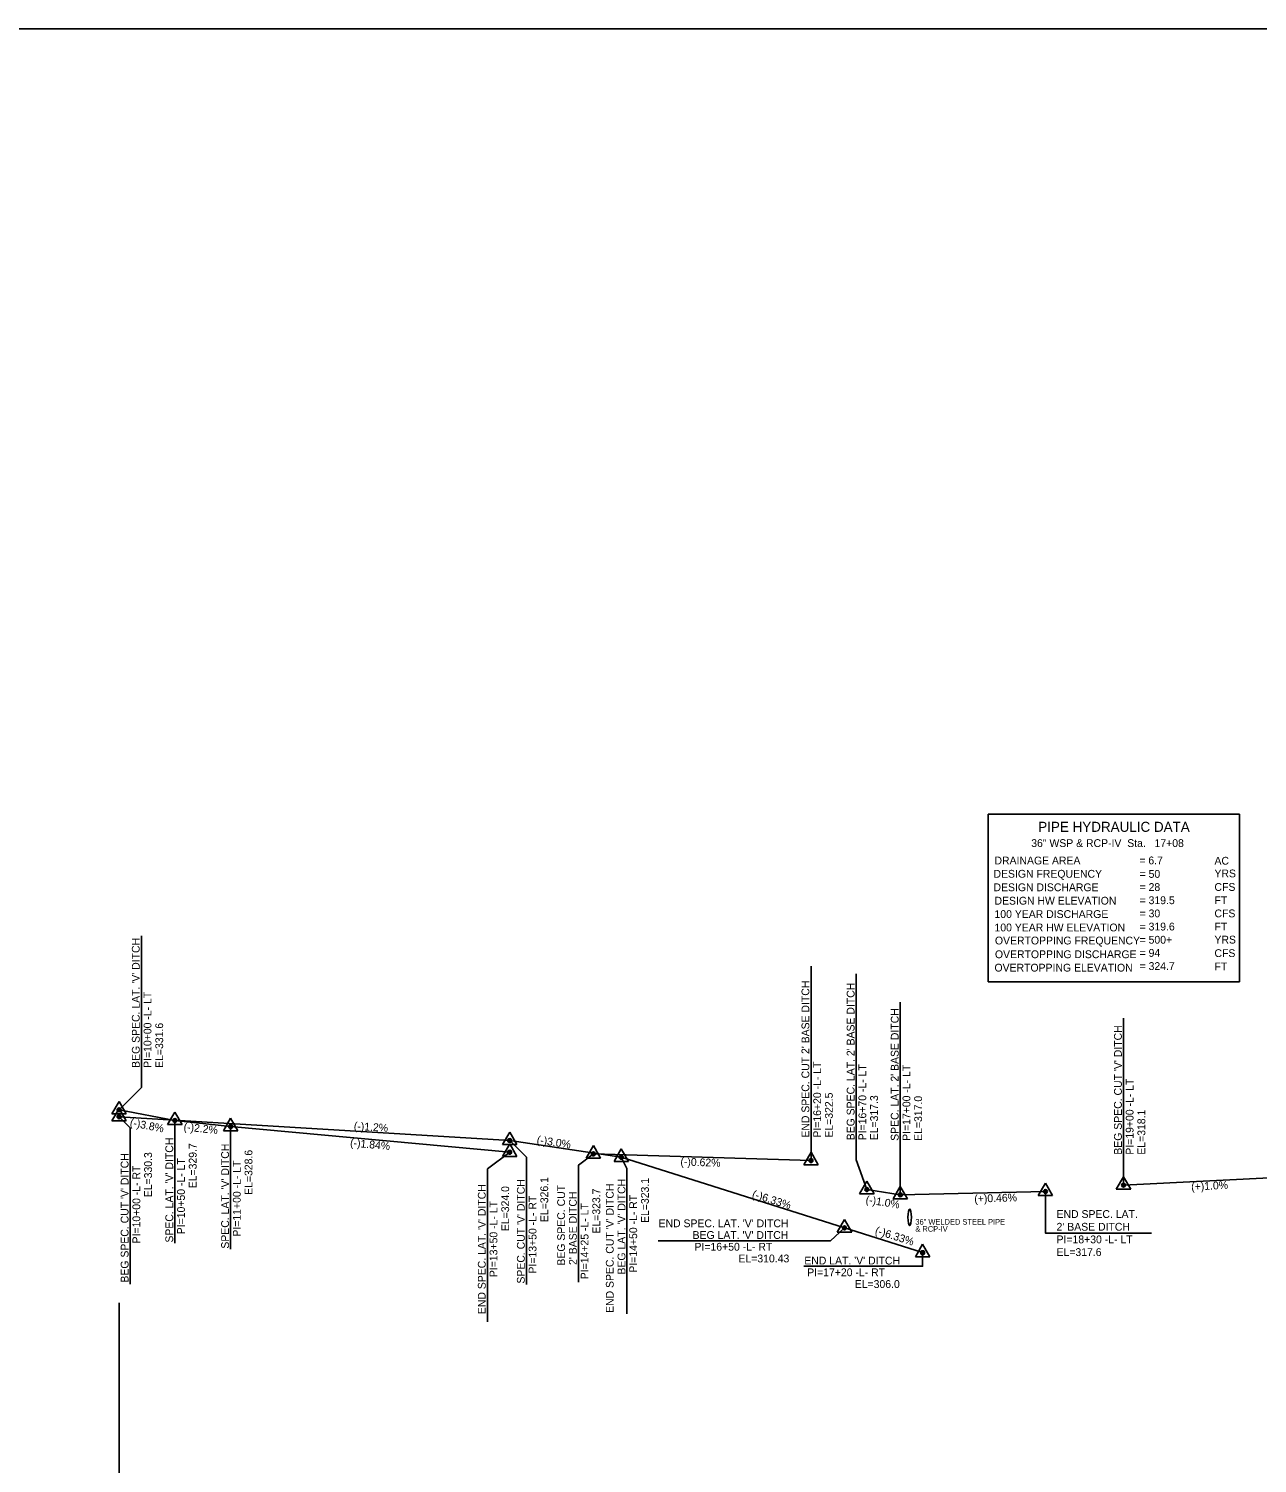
# Model space of a CAD drawing. Extents: x 2110519 to 2119088, y 667494 to 672447.
# Drawn here: x 2112646 to 2113747, y 671161 to 672447 of the extents above; entities that cross this region are included whole.
import ezdxf

# ---------------------------------------------------------------- set-up
doc = ezdxf.new("R2010")
doc.units = 0
for name, color, linetype in [('Exist Horizontal Alignment', 7, 'Continuous'), ('Old_Level_1', 7, 'Continuous'), ('Old_Level_2', 7, 'Continuous'), ('Prop Conc 1ft 6in Curb and Gutter', 7, 'Continuous'), ('Prop Conc 5in Monolithic Surface Mount Island', 7, 'Continuous'), ('Prop Conc Curb 8in x 18in', 7, 'Continuous'), ('Prop EOT', 7, 'Continuous'), ('Prop Paved Shoulder', 7, 'Continuous'), ('Scratch_Level_4', 7, 'Continuous')]:
    doc.layers.add(name, color=color, linetype=linetype)

msp = doc.modelspace()

# ---------------------------------------------------------------- linework, layer by layer
at = {"layer": 'Exist Horizontal Alignment'}
msp.add_line((2112826.7, 671463.2), (2113076.7, 671440.2), dxfattribs=at)
msp.add_lwpolyline([(2110519.2, 672447), (2115845.7, 672447), (2115845.7, 670168.2), (2110519.2, 670168.2)], close=True, dxfattribs=at)
at = {"layer": 'Old_Level_1'}
for p, q in [((2113346.7, 671432.7), (2113346.7, 671606.8)), ((2113626.7, 671410.7), (2113626.7, 671560.4)), ((2112726.7, 671485.7), (2112720.2, 671474.5)), ((2112726.7, 671485.7), (2112733.2, 671474.5)), ((2112720.2, 671474.5), (2112733.2, 671474.5)), ((2112776.7, 671476.1), (2112770.2, 671464.9)), ((2112776.7, 671476.1), (2112783.2, 671464.9)), ((2112776.7, 671468.6), (2112776.7, 671358.6)), ((2112826.7, 671470.7), (2112820.2, 671459.5)), ((2112826.7, 671470.7), (2112833.2, 671459.5)), ((2112770.2, 671464.9), (2112783.2, 671464.9)), ((2112820.2, 671459.5), (2112833.2, 671459.5)), ((2112826.7, 671463.2), (2112826.7, 671353.2)), ((2113076.7, 671447.7), (2113070.2, 671436.5)), ((2113076.7, 671447.7), (2113083.2, 671436.5)), ((2113151.7, 671446.2), (2113145.2, 671435)), ((2113151.7, 671446.2), (2113158.2, 671435)), ((2113070.2, 671436.5), (2113083.2, 671436.5)), ((2113145.2, 671435), (2113158.2, 671435)), ((2113346.7, 671440.2), (2113340.2, 671429)), ((2113340.2, 671429), (2113353.2, 671429)), ((2113346.7, 671440.2), (2113353.2, 671429)), ((2113626.7, 671418.2), (2113620.2, 671407)), ((2113626.7, 671418.2), (2113633.2, 671407)), ((2113396.7, 671414.2), (2113390.2, 671403)), ((2113390.2, 671403), (2113403.2, 671403)), ((2113396.7, 671414.2), (2113403.2, 671403)), ((2113426.7, 671409.5), (2113420.2, 671398.3)), ((2113426.7, 671409.5), (2113433.2, 671398.3)), ((2113556.7, 671412.5), (2113550.2, 671401.3)), ((2113556.7, 671412.5), (2113563.2, 671401.3)), ((2113620.2, 671407), (2113633.2, 671407)), ((2113420.2, 671398.3), (2113433.2, 671398.3)), ((2113550.2, 671401.3), (2113563.2, 671401.3)), ((2112726.7, 670820.2), (2112726.7, 671305.2))]:
    msp.add_line(p, q, dxfattribs=at)
for points in [[(2112726.7, 671478.2), (2112746.7, 671498.2), (2112746.7, 671634.2)], [(2113396.7, 671406.7), (2113387.2, 671433.3), (2113387.2, 671600.1)], [(2113426.7, 671402), (2113426.7, 671574.6)], [(2113076.7, 671440.2), (2113056.7, 671425.2), (2113056.7, 671288.2)], [(2113151.7, 671438.7), (2113138.4, 671428.7), (2113138.4, 671323.8)], [(2113556.7, 671405), (2113556.7, 671367.7), (2113651.8, 671367.7)]]:
    msp.add_lwpolyline(points, dxfattribs=at)
for centre, radius in [((2112726.7, 671478.2), 1.75), ((2112726.7, 671478.2), 1.2), ((2112726.7, 671478.2), 0.5), ((2112776.7, 671468.6), 1.75), ((2112776.7, 671468.6), 1.2), ((2112776.7, 671468.6), 0.5), ((2112826.7, 671463.2), 1.75), ((2112826.7, 671463.2), 1.2), ((2112826.7, 671463.2), 0.5), ((2113076.7, 671440.2), 1.75), ((2113076.7, 671440.2), 1.2), ((2113076.7, 671440.2), 0.5), ((2113151.7, 671438.7), 1.75), ((2113151.7, 671438.7), 1.2), ((2113151.7, 671438.7), 0.5), ((2113346.7, 671432.7), 1.75), ((2113346.7, 671432.7), 1.2), ((2113346.7, 671432.7), 0.5), ((2113396.7, 671406.7), 1.75), ((2113396.7, 671406.7), 1.2), ((2113396.7, 671406.7), 0.5), ((2113426.7, 671402), 1.75), ((2113426.7, 671402), 1.2), ((2113426.7, 671402), 0.5), ((2113556.7, 671405), 1.75), ((2113556.7, 671405), 1.2), ((2113556.7, 671405), 0.5), ((2113626.7, 671410.7), 1.75), ((2113626.7, 671410.7), 1.2), ((2113626.7, 671410.7), 0.5)]:
    msp.add_circle(centre, radius, dxfattribs=at)
at = {"layer": 'Old_Level_2'}
for p, q in [((2113151.7, 671438.7), (2113346.7, 671432.7)), ((2113626.7, 671410.7), (2113776.7, 671418.2)), ((2113396.7, 671406.7), (2113426.7, 671402)), ((2113426.7, 671402), (2113556.7, 671405))]:
    msp.add_line(p, q, dxfattribs=at)
msp.add_lwpolyline([(2112726.7, 671478.2), (2112776.7, 671468.6), (2112826.7, 671463.2), (2113076.7, 671440.2)], dxfattribs=at)
at = {"layer": 'Prop Conc Curb 8in x 18in'}
msp.add_lwpolyline([(2113505.5, 671593), (2113730.5, 671593), (2113730.5, 671743), (2113505.5, 671743)], close=True, dxfattribs=at)
at = {"layer": 'Prop EOT'}
msp.add_lwpolyline([(2112726.7, 671472), (2113076.7, 671450.7), (2113176.7, 671435.7), (2113446.7, 671350.2)], dxfattribs=at)
at = {"layer": 'Prop Paved Shoulder'}
msp.add_ellipse((2113435.1, 671381.9), major_axis=(0, 7.5), ratio=0.2, dxfattribs=at)
at = {"layer": 'Scratch_Level_4'}
for p, q in [((2112726.7, 671479.5), (2112720.2, 671468.3)), ((2112720.2, 671468.3), (2112733.2, 671468.3)), ((2112726.7, 671479.5), (2112733.2, 671468.3)), ((2113076.7, 671458.2), (2113070.2, 671447)), ((2113076.7, 671458.2), (2113083.2, 671447)), ((2113070.2, 671447), (2113083.2, 671447)), ((2113176.7, 671443.2), (2113170.2, 671432)), ((2113176.7, 671443.2), (2113183.2, 671432)), ((2113170.2, 671432), (2113183.2, 671432)), ((2113376.7, 671379.9), (2113370.2, 671368.7)), ((2113376.7, 671379.9), (2113383.2, 671368.7)), ((2113376.7, 671372.4), (2113364.1, 671360.8)), ((2113370.2, 671368.7), (2113383.2, 671368.7)), ((2113364.1, 671360.8), (2113209.8, 671360.8)), ((2113446.7, 671357.7), (2113440.2, 671346.5)), ((2113446.7, 671357.7), (2113453.2, 671346.5)), ((2113440.2, 671346.5), (2113453.2, 671346.5))]:
    msp.add_line(p, q, dxfattribs=at)
for points in [[(2112726.7, 671472), (2112736.7, 671462), (2112736.7, 671322)], [(2113076.7, 671450.7), (2113091.7, 671435.7), (2113091.7, 671321.7)], [(2113176.7, 671435.7), (2113181.7, 671425.7), (2113181.7, 671295.5)], [(2113446.7, 671350.2), (2113446.7, 671338.1), (2113340.3, 671338.1)]]:
    msp.add_lwpolyline(points, dxfattribs=at)
for centre, radius in [((2112726.7, 671472), 1.75), ((2112726.7, 671472), 1.2), ((2112726.7, 671472), 0.5), ((2113076.7, 671450.7), 1.75), ((2113076.7, 671450.7), 1.2), ((2113076.7, 671450.7), 0.5), ((2113176.7, 671435.7), 1.75), ((2113176.7, 671435.7), 1.2), ((2113176.7, 671435.7), 0.5), ((2113376.7, 671372.4), 1.75), ((2113376.7, 671372.4), 1.2), ((2113376.7, 671372.4), 0.5), ((2113446.7, 671350.2), 1.75), ((2113446.7, 671350.2), 1.2), ((2113446.7, 671350.2), 0.5)]:
    msp.add_circle(centre, radius, dxfattribs=at)

# ---------------------------------------------------------------- texts
at = {"layer": 'Old_Level_1'}
for s, rotation, p in [("BEG SPEC. LAT. 'V' DITCH ", 90, (2112745.2, 671515.8)), ('PI=10+00 -L- LT', 90, (2112755.7, 671515.8)), ("END SPEC. CUT 2' BASE DITCH ", 90, (2113345.2, 671453.3)), ("BEG SPEC. LAT. 2' BASE DITCH ", 90, (2113385.7, 671450.9)), ("SPEC. LAT. 2' BASE DITCH ", 90, (2113425.2, 671450.4)), ('EL=331.6', 90, (2112766.2, 671515.8)), ("BEG SPEC. CUT 'V' DITCH ", 90, (2113625.2, 671438)), ('PI=16+20 -L- LT', 90, (2113355.7, 671453.3)), ('PI=16+70 -L- LT', 90, (2113396.2, 671450.9)), ('PI=17+00 -L- LT', 90, (2113435.7, 671450.4)), ('PI=19+00 -L- LT', 90, (2113635.7, 671438)), ('EL=322.5', 90, (2113366.2, 671453.3)), ('EL=317.3', 90, (2113406.7, 671450.9)), ('EL=317.0', 90, (2113446.2, 671450.4)), ('(-)3.8%', 349.0671, (2112736, 671463.7)), ('(-)2.2%', 353.902, (2112784.3, 671459.7)), ('EL=318.1', 90, (2113646.2, 671438)), ("SPEC. LAT. 'V' DITCH ", 90, (2112775.2, 671359.2)), ('EL=329.7', 90, (2112796.2, 671407.9)), ("SPEC. LAT. 'V' DITCH ", 90, (2112825.2, 671353.8)), ('EL=328.6', 90, (2112846.2, 671402)), ('(-)1.84%', 354.7436, (2112933.5, 671445.4)), ('PI=10+50 -L- LT', 90, (2112785.7, 671366.7)), ('PI=11+00 -L- LT', 90, (2112835.7, 671364.6)), ("END SPEC. LAT. 'V' DITCH ", 90, (2113055.2, 671295.1)), ('EL=324.0', 90, (2113076.2, 671369.5)), ('BEG SPEC. CUT ', 90, (2113126.3, 671338.6)), ("2' BASE DITCH ", 90, (2113136.8, 671339.2)), ('EL=323.7', 90, (2113157.8, 671367.3)), ('PI=13+50 -L- LT', 90, (2113065.7, 671328.3)), ('PI=14+25 -L- LT', 90, (2113147.3, 671326.4))]:
    msp.add_text(s, height=7, rotation=rotation, dxfattribs=at).set_placement(p)
for s, p in [("2' BASE DITCH", (2113566.7, 671369.9)), ('END SPEC. LAT.', (2113566.7, 671381.3)), ('PI=18+30 -L- LT', (2113566.7, 671358.6)), ('EL=317.6', (2113566.7, 671347.2))]:
    msp.add_text(s, height=7, dxfattribs=at).set_placement(p)
at = {"layer": 'Old_Level_2'}
for s, rotation, p in [('(-)0.62%', 358.2376, (2113229.6, 671428.3)), ('(+)0.46%', 1.8413, (2113493.1, 671395)), ('(+)1.0%', 2.8624, (2113687.5, 671405.8)), ('(-)1.0%', 351.096, (2113395.3, 671394.5))]:
    msp.add_text(s, height=7, rotation=rotation, dxfattribs=at).set_placement(p)
at = {"layer": 'Prop Conc 1ft 6in Curb and Gutter'}
for s, height, p in [('PIPE HYDRAULIC DATA', 9, (2113550.3, 671727.3)), ('36" WSP & RCP-IV  Sta.   17+08   ', 7, (2113544, 671713.7)), ('DRAINAGE AREA', 7, (2113511.1, 671698.1)), ('= 6.7    ', 7, (2113640.9, 671698.2)), ('AC', 7, (2113708.2, 671697.9)), ('DESIGN FREQUENCY', 7, (2113510.2, 671686.2)), ('= 50 ', 7, (2113641.1, 671686.1)), ('YRS', 7, (2113708.2, 671686.5)), ('DESIGN DISCHARGE', 7, (2113510.2, 671674.1)), ('= 28      ', 7, (2113641.1, 671674.3)), ('CFS', 7, (2113708.2, 671674.4)), ('DESIGN HW ELEVATION', 7, (2113511.1, 671662.1)), ('= 319.5   ', 7, (2113641.1, 671662.5)), ('FT', 7, (2113708.2, 671662.5)), ('100 YEAR DISCHARGE', 7, (2113511.1, 671650.1)), ('= 30      ', 7, (2113641.1, 671650.7)), ('CFS', 7, (2113708.2, 671650.7)), ('100 YEAR HW ELEVATION', 7, (2113511.1, 671638.1)), ('= 319.6   ', 7, (2113641.1, 671638.9)), ('= 500+  ', 7, (2113641.1, 671627.1)), ('YRS', 7, (2113708.2, 671627.2)), ('FT', 7, (2113708.2, 671638.9)), ('OVERTOPPING FREQUENCY', 7, (2113511.5, 671626.4)), ('OVERTOPPING DISCHARGE', 7, (2113511.5, 671614.1)), ('= 94      ', 7, (2113641.1, 671615.3)), ('CFS', 7, (2113708.2, 671615.1)), ('OVERTOPPING ELEVATION', 7, (2113511.1, 671602.1)), ('= 324.7   ', 7, (2113641.1, 671603.5)), ('FT', 7, (2113708.2, 671603.1))]:
    msp.add_text(s, height=height, dxfattribs=at).set_placement(p)
at = {"layer": 'Prop Conc 5in Monolithic Surface Mount Island'}
for s, p in [('36" WELDED STEEL PIPE ', (2113440.2, 671375.3)), ('& RCP-IV', (2113440.2, 671369))]:
    msp.add_text(s, height=5, dxfattribs=at).set_placement(p)
at = {"layer": 'Scratch_Level_4'}
for s, rotation, p in [('(-)1.2%', 356.5347, (2112936.9, 671460.3)), ('(-)3.0%', 351.4692, (2113100.6, 671448.1)), ("BEG SPEC. CUT 'V' DITCH ", 90, (2112735.2, 671323.4)), ('EL=330.3', 90, (2112756.2, 671399.9)), ('PI=10+00 -L- RT', 90, (2112745.7, 671358.5)), ('EL=326.1', 90, (2113111.2, 671377.6)), ("BEG LAT. 'V' DITCH ", 90, (2113180.4, 671330.6)), ('EL=323.1', 90, (2113201.4, 671376.8)), ("SPEC. CUT 'V' DITCH ", 90, (2113090.2, 671322.5)), ("END SPEC. CUT 'V' DITCH", 90, (2113169.9, 671296.2)), ('(-)6.33%', 342.4287, (2113293.3, 671399.8)), ('PI=13+50 -L- RT', 90, (2113100.7, 671331.5)), ('PI=14+50 -L- RT', 90, (2113190.9, 671332.3)), ("END SPEC. LAT. 'V' DITCH ", 360, (2113210.1, 671373)), ("BEG LAT. 'V' DITCH", 360, (2113240.6, 671362.5)), ('(-)6.33%', 342.4287, (2113403.5, 671367.2)), ('PI=16+50 -L- RT', 360, (2113242.3, 671352)), ('EL=310.43', 360, (2113281.7, 671341.5)), ("END LAT. 'V' DITCH ", 360, (2113340.7, 671339.6)), ('PI=17+20 -L- RT', 360, (2113343.3, 671329.1)), ('EL=306.0', 360, (2113385.9, 671318.6))]:
    msp.add_text(s, height=7, rotation=rotation, dxfattribs=at).set_placement(p)

doc.saveas('drawing.dxf')
